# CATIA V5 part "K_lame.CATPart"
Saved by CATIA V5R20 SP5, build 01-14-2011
Part number: lame
Publications: "Plan.4", "Point.2", "Plan.3"
Bounding box of the stored display mesh (mm): x 165.794 to 204.175, y -113.311 to -45.028, z 224.027 to 287.027
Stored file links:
  G:\Khaled_CFAO_2011\SIL\SIL_GR2\pfradet\pfradet\Khaled\CAD_ThinkMOTION\K_lame.CATPart
  U:\TNHIKMOTION\ass_cutting_device.CATProduct
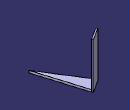
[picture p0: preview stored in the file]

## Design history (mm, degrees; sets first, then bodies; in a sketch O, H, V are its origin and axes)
Sketch1 on Plane1, origin (123.6064, 33.6854, 227.0274), H (0.9898, -0.1427, 0), V (-0.1427, -0.9898, 0)
  line L1 (57, 83) -> (71, 71)
  line L2 (71, 71) -> (100.7143, 134)
  line L3 (57, 83) -> (100.7143, 134)
  perpendicularity: L3 L1
Pad1: profile Sketch1, direction (0, 0, -1), length 3
Sketch2 on Plane2, origin (85.3521, -106.7945, 0), H (0.8443, 0.5358, 0), V (0, 0, 1)
  line L1 (95.2731, 287.0274) -> (115.2731, 287.0274)
  line L2 (115.2731, 287.0274) -> (115.2731, 227.0274)
  line L3 (115.2731, 227.0274) -> (95.2731, 227.0274)
  line L4 (95.2731, 227.0274) -> (95.2731, 287.0274)
  reference projected point E1 (104.7731, 277.0274) from Point1
  reference projected point E2 (104.7731, 277.0274) from Point1
  distance E1 L2 = 10.5
  distance E2 L1 = 10
  horizontal: L1 H, L3 H
  vertical: L2 V, L4 V
Pad2: profile Sketch2, direction (0.5358, -0.8443, 0), length 2
Plane1: type 2Lines, Element1 edge [face of Pad2 from Sketch2.L3 | end face of Pad2], Element2 edge [start face of Pad2 | face of Pad2 from Sketch2.L3]
Set1
  Plane2: linked copy from another document
  Point1: linked copy from another document
Body1 (main body)
  Pad3: profile face of Pad2 from Sketch2.L3, direction along face of Pad2 from Sketch2.L3, length 3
